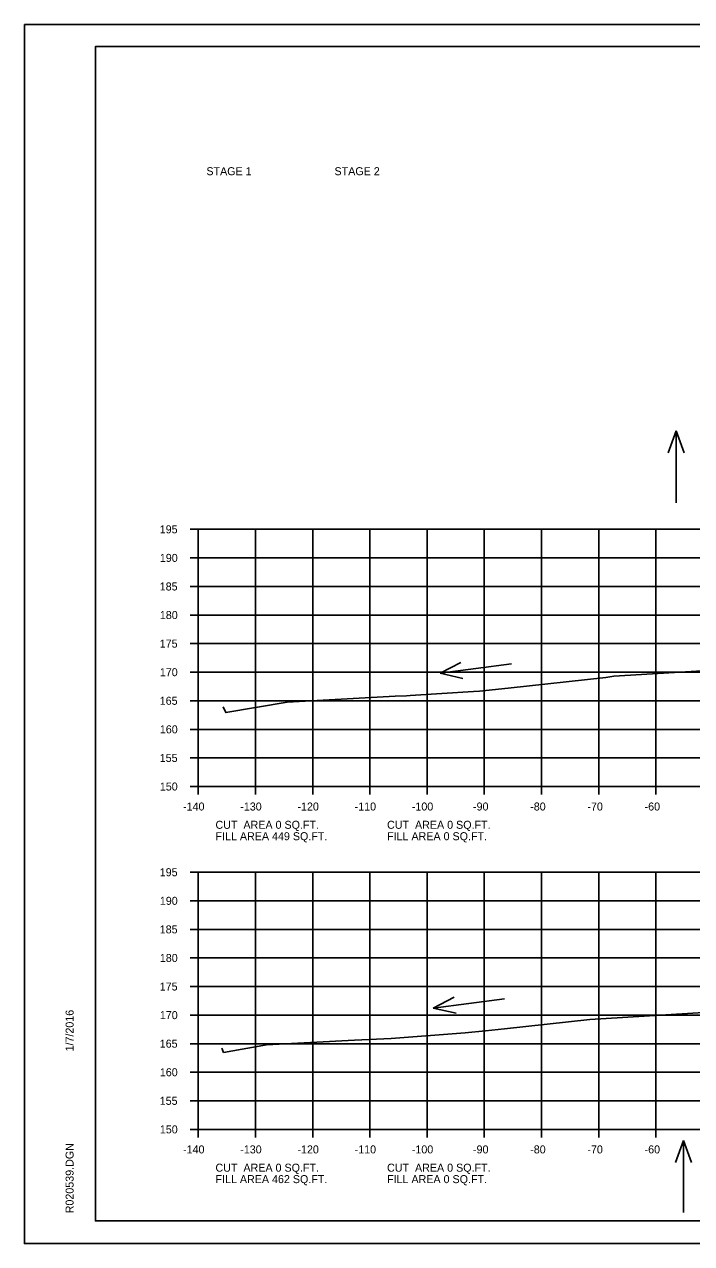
# Model space of a CAD drawing. Extents: x 915787 to 919910, y 133456 to 136717.
# Drawn here: x 916243.6 to 916360.2, y 134096 to 134309.4 of the extents above; entities that cross this region are included whole.
import ezdxf

# ---------------------------------------------------------------- set-up
doc = ezdxf.new("R2010")
doc.units = 0
for name, color, linetype in [('R_Axis', 7, 'Continuous'), ('R_Axis Annot', 7, 'Continuous'), ('R_Border', 7, 'Continuous'), ('R_Border Notes', 7, 'Continuous'), ('R_Exist Surface', 7, 'Continuous'), ('R_Grid', 7, 'Continuous'), ('R_No Plot', 7, 'Continuous'), ('R_Water Annot', 7, 'Continuous')]:
    doc.layers.add(name, color=color, linetype=linetype)

msp = doc.modelspace()

# ---------------------------------------------------------------- linework, layer by layer
at = {"layer": 'R_Axis'}
for p, q in [((916272.58, 134221.03), (916273.98, 134221.03)), ((916273.98, 134176.03), (916273.98, 134221.03)), ((916272.58, 134216.03), (916273.98, 134216.03)), ((916272.58, 134211.03), (916273.98, 134211.03)), ((916272.58, 134206.03), (916273.98, 134206.03)), ((916272.58, 134201.03), (916273.98, 134201.03)), ((916272.58, 134196.03), (916273.98, 134196.03)), ((916272.58, 134191.03), (916273.98, 134191.03)), ((916272.58, 134186.03), (916273.98, 134186.03)), ((916272.58, 134181.03), (916273.98, 134181.03)), ((916272.58, 134176.03), (916273.98, 134176.03)), ((916273.98, 134176.03), (916553.98, 134176.03)), ((916273.98, 134174.63), (916273.98, 134176.03)), ((916283.98, 134174.63), (916283.98, 134176.03)), ((916293.98, 134174.63), (916293.98, 134176.03)), ((916303.98, 134174.63), (916303.98, 134176.03)), ((916313.98, 134174.63), (916313.98, 134176.03)), ((916323.98, 134174.63), (916323.98, 134176.03)), ((916333.98, 134174.63), (916333.98, 134176.03)), ((916343.98, 134174.63), (916343.98, 134176.03)), ((916353.98, 134174.63), (916353.98, 134176.03)), ((916272.58, 134161.03), (916273.98, 134161.03)), ((916273.98, 134116.03), (916273.98, 134161.03)), ((916272.58, 134156.03), (916273.98, 134156.03)), ((916272.58, 134151.03), (916273.98, 134151.03)), ((916272.58, 134146.03), (916273.98, 134146.03)), ((916272.58, 134141.03), (916273.98, 134141.03)), ((916272.58, 134136.03), (916273.98, 134136.03)), ((916272.58, 134131.03), (916273.98, 134131.03)), ((916272.58, 134126.03), (916273.98, 134126.03)), ((916272.58, 134121.03), (916273.98, 134121.03)), ((916272.58, 134116.03), (916273.98, 134116.03)), ((916273.98, 134116.03), (916553.98, 134116.03)), ((916273.98, 134114.63), (916273.98, 134116.03)), ((916283.98, 134114.63), (916283.98, 134116.03)), ((916293.98, 134114.63), (916293.98, 134116.03)), ((916303.98, 134114.63), (916303.98, 134116.03)), ((916313.98, 134114.63), (916313.98, 134116.03)), ((916323.98, 134114.63), (916323.98, 134116.03)), ((916333.98, 134114.63), (916333.98, 134116.03)), ((916343.98, 134114.63), (916343.98, 134116.03)), ((916353.98, 134114.63), (916353.98, 134116.03))]:
    msp.add_line(p, q, dxfattribs=at)
at = {"layer": 'R_Border'}
for p, q in [((916255.98, 134305.49), (916572.16, 134305.49)), ((916255.98, 134100.03), (916255.98, 134305.49)), ((916255.98, 134100.03), (916255.98, 134100.03)), ((916572.16, 134100.03), (916255.98, 134100.03))]:
    msp.add_line(p, q, dxfattribs=at)
at = {"layer": 'R_Exist Surface'}
for points in [[(916278.35, 134189.97), (916278.79, 134188.95), (916289.5, 134190.79), (916308.38, 134191.84), (916310.38, 134191.9), (916311.01, 134191.96), (916322.11, 134192.67), (916323.17, 134192.74), (916328.17, 134193.24), (916345.25, 134195.1), (916346.62, 134195.32), (916365.93, 134196.48)], [(916278.08, 134130.22), (916278.39, 134129.5), (916285.89, 134130.8), (916301.27, 134131.66), (916307.7, 134131.94), (916320.61, 134132.93), (916324.18, 134133.29), (916327.52, 134133.63), (916342.44, 134135.26), (916345.29, 134135.45), (916363.32, 134136.53)]]:
    msp.add_lwpolyline(points, dxfattribs=at)
at = {"layer": 'R_Grid'}
for p, q in [((916273.98, 134221.03), (916553.98, 134221.03)), ((916273.98, 134176.03), (916273.98, 134221.03)), ((916283.98, 134176.03), (916283.98, 134221.03)), ((916293.98, 134176.03), (916293.98, 134221.03)), ((916303.98, 134176.03), (916303.98, 134221.03)), ((916313.98, 134176.03), (916313.98, 134221.03)), ((916323.98, 134176.03), (916323.98, 134221.03)), ((916333.98, 134176.03), (916333.98, 134221.03)), ((916343.98, 134176.03), (916343.98, 134221.03)), ((916353.98, 134176.03), (916353.98, 134221.03)), ((916273.98, 134216.03), (916553.98, 134216.03)), ((916273.98, 134211.03), (916553.98, 134211.03)), ((916273.98, 134206.03), (916553.98, 134206.03)), ((916273.98, 134201.03), (916553.98, 134201.03)), ((916273.98, 134196.03), (916553.98, 134196.03)), ((916273.98, 134191.03), (916553.98, 134191.03)), ((916273.98, 134186.03), (916553.98, 134186.03)), ((916273.98, 134181.03), (916553.98, 134181.03)), ((916273.98, 134176.03), (916553.98, 134176.03)), ((916273.98, 134161.03), (916553.98, 134161.03)), ((916273.98, 134116.03), (916273.98, 134161.03)), ((916283.98, 134116.03), (916283.98, 134161.03)), ((916293.98, 134116.03), (916293.98, 134161.03)), ((916303.98, 134116.03), (916303.98, 134161.03)), ((916313.98, 134116.03), (916313.98, 134161.03)), ((916323.98, 134116.03), (916323.98, 134161.03)), ((916333.98, 134116.03), (916333.98, 134161.03)), ((916343.98, 134116.03), (916343.98, 134161.03)), ((916353.98, 134116.03), (916353.98, 134161.03)), ((916273.98, 134156.03), (916553.98, 134156.03)), ((916273.98, 134151.03), (916553.98, 134151.03)), ((916273.98, 134146.03), (916553.98, 134146.03)), ((916273.98, 134141.03), (916553.98, 134141.03)), ((916273.98, 134136.03), (916553.98, 134136.03)), ((916273.98, 134131.03), (916553.98, 134131.03)), ((916273.98, 134126.03), (916553.98, 134126.03)), ((916273.98, 134121.03), (916553.98, 134121.03)), ((916273.98, 134116.03), (916553.98, 134116.03))]:
    msp.add_line(p, q, dxfattribs=at)
at = {"layer": 'R_No Plot'}
for p, q in [((916243.57, 134309.38), (916576.91, 134309.38)), ((916243.57, 134096.05), (916576.91, 134096.05))]:
    msp.add_line(p, q, dxfattribs=at)
for points in [[(916243.57, 134309.38), (916576.91, 134309.38), (916576.91, 134096.05), (916243.57, 134096.05)], [(916489.9, 134305.49), (916489.9, 134295.61), (916525.63, 134295.61), (916525.63, 134292.69), (916548.83, 134292.69), (916548.83, 134269.47), (916572.16, 134269.47), (916572.16, 134100.03), (916255.98, 134100.03), (916255.98, 134305.49)]]:
    msp.add_lwpolyline(points, close=True, dxfattribs=at)
at = {"layer": 'R_Water Annot'}
for p, q in [((916357.52, 134238.26), (916356.12, 134234.42)), ((916357.52, 134225.69), (916357.52, 134238.26)), ((916357.52, 134238.26), (916358.92, 134234.42)), ((916316.25, 134195.84), (916319.88, 134197.73)), ((916328.71, 134197.47), (916316.25, 134195.84)), ((916316.25, 134195.84), (916320.25, 134194.95)), ((916315.06, 134137.27), (916318.7, 134139.16)), ((916327.53, 134138.9), (916315.06, 134137.27)), ((916315.06, 134137.27), (916319.06, 134136.38)), ((916358.8, 134114.06), (916357.4, 134110.22)), ((916358.8, 134101.5), (916358.8, 134114.06)), ((916358.8, 134114.06), (916360.2, 134110.22))]:
    msp.add_line(p, q, dxfattribs=at)

# ---------------------------------------------------------------- texts
at = {"layer": 'R_Axis Annot'}
for s, p in [('195', (916267.23, 134220.33)), ('190', (916267.25, 134215.33)), ('185', (916267.23, 134210.33)), ('180', (916267.25, 134205.33)), ('175', (916267.23, 134200.33)), ('170', (916267.25, 134195.33)), ('165', (916267.23, 134190.33)), ('160', (916267.25, 134185.33)), ('155', (916267.23, 134180.33)), ('150', (916267.25, 134175.33)), ('-140', (916271.31, 134171.83)), ('-130', (916281.31, 134171.83)), ('-120', (916291.31, 134171.83)), ('-110', (916301.31, 134171.83)), ('-100', (916311.31, 134171.83)), ('-90', (916322.01, 134171.83)), ('-80', (916332.01, 134171.83)), ('-70', (916342.01, 134171.83)), ('-60', (916352.01, 134171.83)), ('195', (916267.23, 134160.33)), ('190', (916267.25, 134155.33)), ('185', (916267.23, 134150.33)), ('180', (916267.25, 134145.33)), ('175', (916267.23, 134140.33)), ('170', (916267.25, 134135.33)), ('165', (916267.23, 134130.33)), ('160', (916267.25, 134125.33)), ('155', (916267.23, 134120.33)), ('150', (916267.25, 134115.33)), ('-140', (916271.31, 134111.83)), ('-130', (916281.31, 134111.83)), ('-120', (916291.31, 134111.83)), ('-110', (916301.31, 134111.83)), ('-100', (916311.31, 134111.83)), ('-90', (916322.01, 134111.83)), ('-80', (916332.01, 134111.83)), ('-70', (916342.01, 134111.83)), ('-60', (916352.01, 134111.83))]:
    msp.add_text(s, height=1.4, dxfattribs=at).set_placement(p)
at = {"layer": 'R_Border'}
for s, p in [('1/7/2016', (916252.17, 134129.67)), ('R020539.DGN', (916252.17, 134101.35))]:
    msp.add_text(s, height=1.4, rotation=90, dxfattribs=at).set_placement(p)
at = {"layer": 'R_Border Notes'}
for s, p in [('STAGE 1', (916275.39, 134282.99)), ('STAGE 2', (916297.79, 134282.99)), ('CUT  AREA 0 SQ.FT.', (916276.98, 134168.63)), ('FILL AREA 449 SQ.FT.', (916276.98, 134166.63)), ('CUT  AREA 0 SQ.FT.', (916306.98, 134168.63)), ('FILL AREA 0 SQ.FT.', (916306.98, 134166.63)), ('CUT  AREA 0 SQ.FT.', (916276.98, 134108.63)), ('CUT  AREA 0 SQ.FT.', (916306.98, 134108.63)), ('FILL AREA 462 SQ.FT.', (916276.98, 134106.63)), ('FILL AREA 0 SQ.FT.', (916306.98, 134106.63))]:
    msp.add_text(s, height=1.4, dxfattribs=at).set_placement(p)

doc.saveas('drawing.dxf')
